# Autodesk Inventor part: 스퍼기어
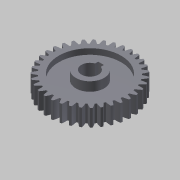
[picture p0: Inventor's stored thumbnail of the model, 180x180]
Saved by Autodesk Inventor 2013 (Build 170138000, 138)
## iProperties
Created: 2013-08
Part Number: 스퍼기어
Material: 강
Document SubType Name: Modeling
Designer: 한국산업디자인학원
Categories: <?xml version="1.0" encoding="UTF-16"?> <MemberInstance><Categories><FamilyTemplate><FamilyTemplateParameter ValueType="xs:double" Id="1" ObjectReferenceKey="da
Density: 1 g/cm^3
CustomPartVersion: 1
Author: 한국산업디자인학원
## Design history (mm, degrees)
sketch "Sketch1"
  geometry: C1 r 37 at (0, 0)
  constraints: 1 centre point
  dimensions: "d0" = 74 diameter of C1 (= da_da)
extrude "Extrusion1" new body sketch "Sketch1" distance "d1" = 15 (= da_b); taper "d2" = 0 deg
workplane "Work Plane2"
feature "피치 지름" dims "d4" = 10, "d5" = 0
workplane "Work Plane8"
workplane "Work Plane9"
feature "스퍼 기어" dims "da_b" = 15, "da_d" = 70, "da_aw" = 70, "da_da" = 74, "da_df" = 65, "da_dw" = 70, angle "da_beta" = 0 deg, "da_lefttooth" = 0, "da_righttooth" = 0
sketch "스케치3"
  geometry: L1 (0, 0)-(0, 15); L2 (0, 0)-(12.5, 0); L3 (12.5, 0)-(12.5, 5); L4 (12.5, 5)-(27.5, 5); L5 (27.5, 5)-(27.5, 0); L6 (27.5, 0)-(32.75, 0); L7 (32.75, 0)-(32.75, 15); L8 (32.75, 15)-(27.5, 15); L9 (27.5, 15)-(27.5, 10); L10 (27.5, 10)-(12.5, 10); L11 (12.5, 10)-(12.5, 15); L12 (12.5, 15)-(0, 15); L13 (12.5, 10)-(0, 10); L14 (12.5, 5)-(0, 5); L15 (27.5, 15)-(12.5, 15); L16 (12.5, 10)-(12.5, 5); L17 (27.5, 10)-(27.5, 5); L18 (27.5, 0)-(12.5, 0); L19 (12.5, 15)-(0, 15); L20 (0, 0)-(12.5, 0); L21 (12.5, 10)-(0, 10); L22 (12.5, 5)-(0, 5)
  constraints: 44 end point, 8 parallel, 5 collinear, 5 perpendicular, 4 equal length, 2 point on line, 1 vertical
  dimensions: "d49" = 55 diameter of L9 L1; "d51" = 15 distance of L1.start L1.end; "d52" = 5 distance of L3.end L2.end; "d53" = 25 diameter of L2.end L1; "d54" = 65.5 diameter of L7 L1; "d55" = 15 distance of L7.end L6.end
revolve "회전1" sketch "스케치3" stored, may be unused: angle "d56" = 90 deg
sketch "스케치4"
  geometry: C1 r 12.5 at (0, 0) reference; C2 r 12.5 at (0, 0)
  constraints: 1 centre point, 1 coincident, 1 concentric
extrude "돌출2" join sketch "스케치4" distance "d57" = 13; taper "d58" = 0 deg
sketch "스케치5"
  geometry: C1 r 12.5 at (0, 0) reference; C2 r 12.5 at (0, 0)
  constraints: 1 centre point, 1 coincident, 1 concentric
extrude "돌출3" join sketch "스케치5" distance "d59" = 3; taper "d60" = 0 deg
sketch "스케치6"
  geometry: L1 (-2.5, 9.8)-(2.5, 9.8); L2 (2.5, 9.8)-(2.5, 7.071); L3 (-2.5, 9.8)-(-2.5, 7.071); C1 r 12.5 at (0, 0) reference; A1 r 7.5 centre (0, 0) between (-2.5, 7.071) and (2.5, 7.071); 1 further point
  constraints: 6 end point, 2 point on circle, 1 centre point, 1 coincident, 1 horizontal, 1 midpoint, 1 parallel, 1 perpendicular, 1 vertical alignment
  dimensions: "d61" = 5 distance of L1.start L1.end; "d63" = 15 diameter of A1; "d64" = 9.8 distance of C1.centre point (0, 9.8)
extrude "돌출4" cut sketch "스케치6" stored distance "d65" = 3; taper "d66" = 0 deg
body "Solid1"
sketch "Sketch2"
  geometry: C1 r 37 at (0, 0) reference; C2 r 35 at (0, 0)
  constraints: 1 centre point, 1 coincident
  dimensions: "d3" = 70 diameter of C2 (= da_dw)
body "Srf1"
other parameters: "d17" = 0, "d34" = 0.8976 (computed from da_z), "d39" = 0, "d41" = 0, "d47" = 0, "d48" = 0
